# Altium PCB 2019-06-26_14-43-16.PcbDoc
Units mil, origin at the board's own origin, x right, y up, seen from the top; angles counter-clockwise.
Board outline 2600 x 1500 mil, 4 copper layers (Top Layer, MidLayer1, MidLayer2, Bottom Layer); 20 components, 9 nets, 52 pads, 82 vias.
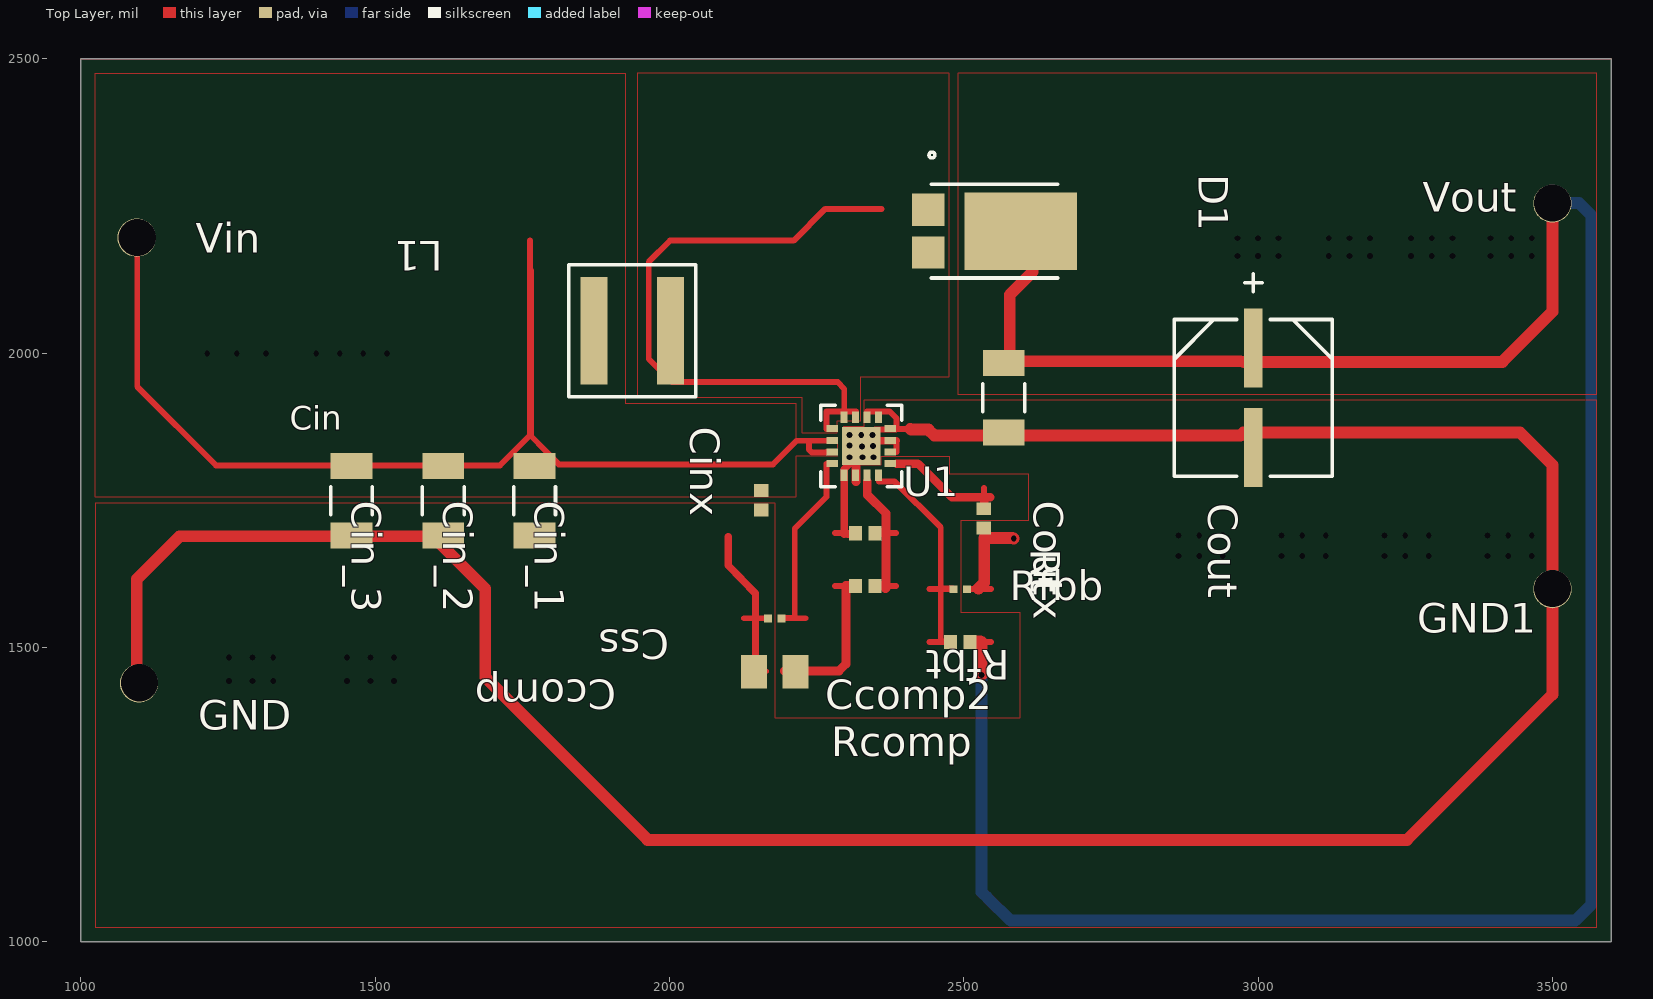
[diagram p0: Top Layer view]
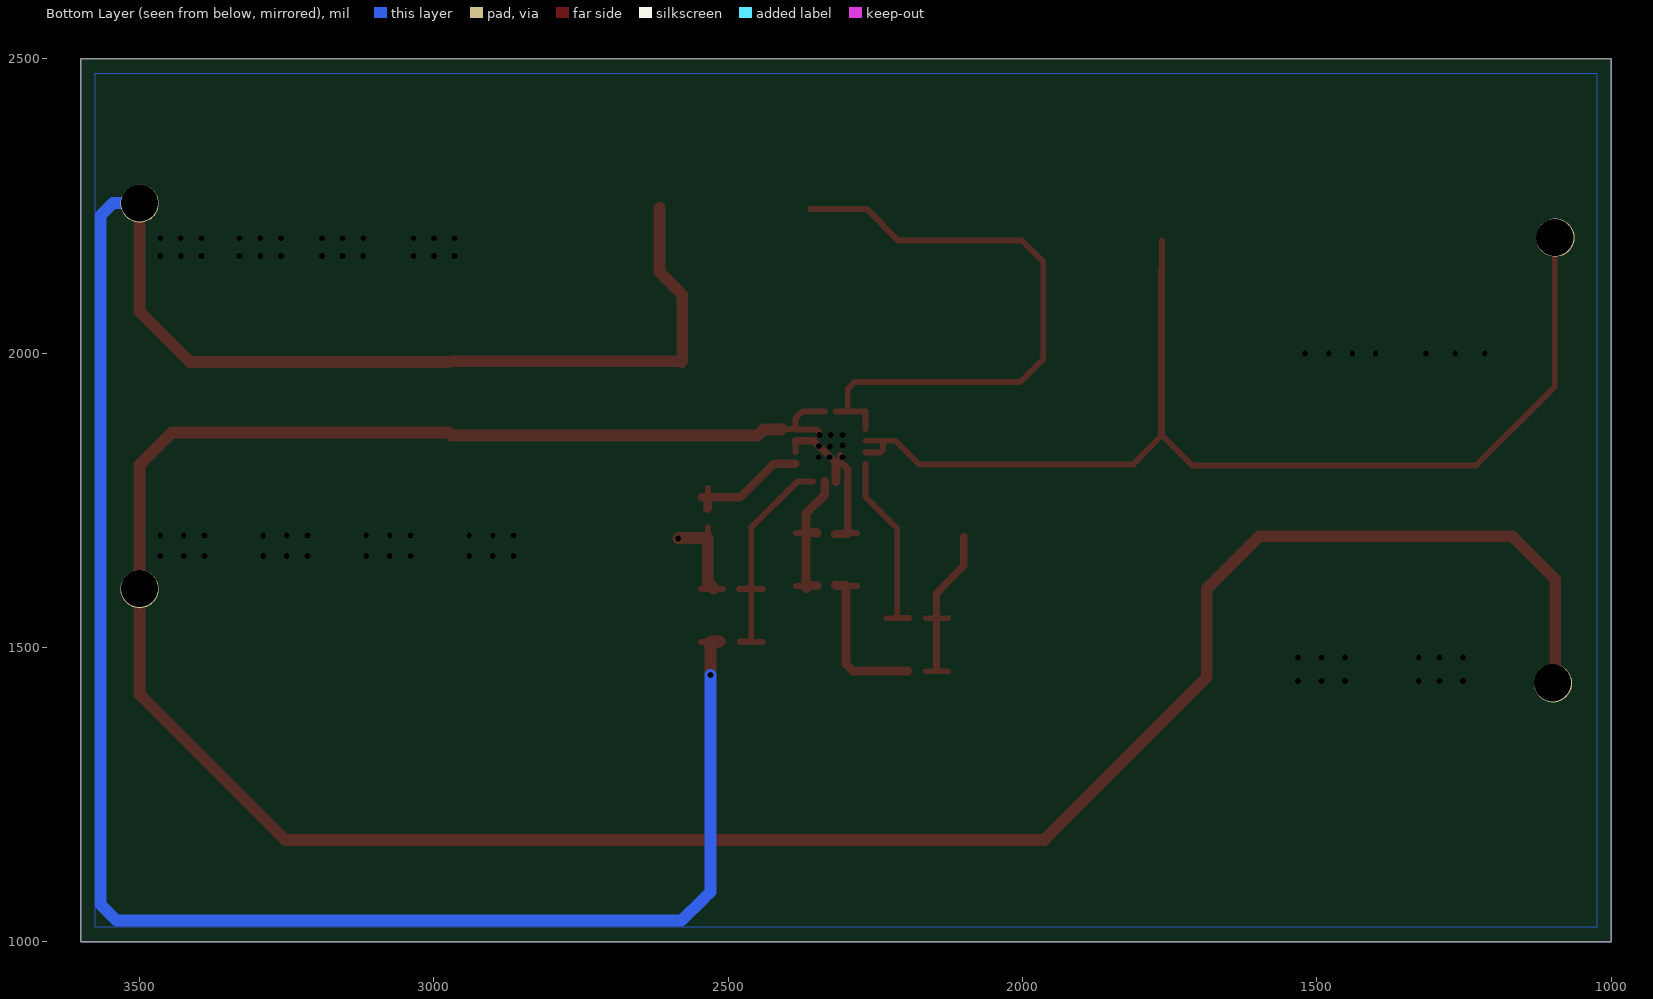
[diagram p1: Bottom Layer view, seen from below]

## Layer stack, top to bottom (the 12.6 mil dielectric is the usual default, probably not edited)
Top Layer: signal copper 1.4
Dielectric: core 12.6, FR-4, Dk 4.8
MidLayer1: signal copper 1.4
Dielectric: prepreg 12.6, FR-4, Dk 4.8
MidLayer2: signal copper 1.4
Dielectric: core 12.6, FR-4, Dk 4.8
Bottom Layer: signal copper 1.4

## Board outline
1000,1000 3600,1000 3600,2500 1000,2500

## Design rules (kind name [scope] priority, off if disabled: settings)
PlaneConnect [All] p0: scope1count=1 scope1_0_kind=Board scope1_0_value=Board scope2count=1 scope2_0_kind=Board scope2_0_value=Board commentlength=0 planeconnectstyle=Direct reliefexpansion=20 reliefentries=4 reliefconductorwidth=10 reliefairgap=10
PlaneConnect [All] p1: planeconnectstyle=Direct reliefexpansion=20 reliefentries=4 reliefconductorwidth=10 reliefairgap=10
PolygonConnect [All] p0: scope1count=1 scope1_0_kind=Board scope1_0_value=Board scope2count=1 scope2_0_kind=Board scope2_0_value=Board commentlength=0 connectstyle=Direct reliefconductorwidth=10 reliefentries=4 polygonreliefangle="90 Angle"
PolygonConnect [All] p1: connectstyle=Direct reliefconductorwidth=10 reliefentries=4 polygonreliefangle="90 Angle"

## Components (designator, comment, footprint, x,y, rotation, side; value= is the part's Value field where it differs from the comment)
Ccomp "" 0805 2179,1459 r180 top
Ccomp2 "" 0402 2333,1694 r0 top
Cin_1 "" 1206_190 1771,1749 r270 top
Cin_2 "" 1206_190 1616,1749 r270 top
Cin_3 "" 1206_190 1460,1749 r270 top
Cinx "" 0402 2156,1750 r270 top
Cout "" CAPSMT_62_F61 2992,1924 r270 top
Coutx "" 1206 2568,1924 r270 top
Css "" 0201 2179,1549 r180 top
D1 "" POWERDI5 2552,2207 r270 top
GND "" TP-5012 1099,1439 r0 top
GND1 "" TP-5012 3500,1599 r0 top
L1 "" XAL5030 1937,2038 r180 top
Rcomp "" 0402 2333,1604 r0 top
Rfbb "" 0201 2494,1599 r0 top
Rfbt "" 0402 2494,1509 r180 top
Rt "" 0402 2534,1719 r270 top
U1 "" S-PWQFN-N16 2326,1842 r0 top
Vin "" TP-5012 1095,2196 r0 top
Vout "" TP-5012 3500,2254 r0 top

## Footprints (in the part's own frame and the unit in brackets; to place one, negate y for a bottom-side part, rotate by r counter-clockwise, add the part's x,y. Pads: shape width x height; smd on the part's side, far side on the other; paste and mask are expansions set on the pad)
0201 [mil]
  rect 14x13 smd: 1(-11.5,0) 2(11.5,0)
0402 [mil]
  rect 22x24 smd: 1(-16.5,0) 2(16.5,0)
0805 [mil]
  rect 44x57 smd: 1(-35.5,0) 2(35.5,0)
1206 [mil]
  rect 44x71 smd: 1(-59,0) 2(59,0)
  silkscreen extent -24,-36 24,36
1206_190 [mil]
  rect 44x71 smd: 1(-59,0) 2(59,0)
  silkscreen extent -24,-36 24,36
CAPSMT_62_F61 [mil]
  rect 134x31 smd: 1(-84.5,0) 2(84.5,0)
  silkscreen extent -210,-134 133,134
POWERDI5 [mil]
  rect 55x55 smd: 1(-36.22,-112.5) 3(36.22,-112.5)
  rect 132x191 smd: 2(0,44.5)
  silkscreen extent -134,-111 80,108
S-PWQFN-N16 [mm]
  rect 0.5x0.3 smd: 1(-1.25,0.75) 2(-1.25,0.25) 3(-1.25,-0.25) 4(-1.25,-0.75) 9(1.25,-0.75) 10(1.25,-0.25) 11(1.25,0.25) 12(1.25,0.75)
  rect 0.3x0.5 smd: 5(-0.75,-1.25) 6(-0.25,-1.25) 7(0.25,-1.25) 8(0.75,-1.25) 13(0.75,1.25) 14(0.25,1.25) 15(-0.25,1.25) 16(-0.75,1.25)
  rect 1.65x1.65 smd: 17(0,0)
  silkscreen extent -1.75,-1.75 1.75,1.75
TP-5012 [mil]
  round 65 / inner round 0 / far side round 65 hole 32: 1(0,0)
XAL5030 [mil]
  rect 46x183 smd: 1(-65,0) 2(65,0)
  silkscreen extent -108,-112 108,112

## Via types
v1: diameter 0, hole 10, Top Layer to Bottom Layer, 78 vias
v2: diameter 0, hole 63, Top Layer to Bottom Layer, 4 vias

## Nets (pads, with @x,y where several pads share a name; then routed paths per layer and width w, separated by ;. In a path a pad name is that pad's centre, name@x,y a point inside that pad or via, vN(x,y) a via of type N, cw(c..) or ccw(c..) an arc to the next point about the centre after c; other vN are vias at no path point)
0: Ccomp2.1 Ccomp.2 Cin_1.2 Cin_2.2 Cin_3.2 Cinx.2 Cout.2 Coutx.2 Css.2 GND1.1 GND.1 Rfbb.2 Rt.2 U1.5 U1.6 U1.10 U1.11 U1.12 U1.13 U1.14 U1.17 | length 5539.2
  Top Layer w10: Ccomp.2@2127,1459.5 Ccomp.2@2164,1459.5 ; 2127,1549.5 Css.2@2164,1549.5 ; 2281,1694.5 Ccomp2.1@2318,1694.5 ; U1.14@2336,1901 2356,1901 2374,1901 2386,1889 2386,1871 ; U1.17@2346,1860 2346,1867 2349,1870 2385,1870 2386,1871 ; 2386,1832 2386,1851 ; 2409,1871 2386,1871 ; Rfbb.2@2509,1599.5 2546,1599.5 ; 2534.5,1667 Rt.2@2534.5,1704 ; 2975,1865 Cout.2@2980,1870
  Top Layer w12: 2100,1688 2100,1639 2146,1592 2146,1550 Ccomp.2@2146,1460 ; 2297,1692 2297,1695 ; 2297,1701 2297,1782 2297,1803 2310,1816 U1.17@2310,1826 ; 2300,1695 2303,1692 Ccomp2.1@2320,1692 ; U1.17@2317,1813 v1(2346,1842) 2355,1851 2386,1851
  Top Layer w15: 2317,1782 U1.17@2317,1813
  Top Layer w20: GND.1@1095,1440 1095,1616 1168,1689 1420,1689 1598,1689 1687,1600 1687,1449 1963,1173 3253,1173 3500,1420 v2(3500,1600) 3500,1810 3445,1865 2976,1865 2975,1865 2970,1860 2450,1860 2440,1870 2411,1870 2409,1871 ; 2525,1600 2535,1610 2535,1686 2583,1686 v1(2585,1685)
  other v1: 1252,1443 1292,1443 1327,1443 1452,1443 1492,1443 1532,1443 1252,1483 1292,1483 1327,1483 1452,1483 1492,1483 1532,1483 2865,1655 2900,1655 2940,1655 3040,1655 3075,1655 3115,1655 3215,1655 3250,1655 3290,1655 3390,1655 3425,1655 3465,1655 2865,1690 2900,1690 2940,1690 3040,1690 3075,1690 3115,1690 3215,1690 3250,1690 3290,1690 3390,1690 3425,1690 3465,1690 2306,1823 2328,1823 2347,1823 2327,1841 2306,1843 2306,1861 2326,1861 2345,1861
  other v2: 1100,1440
1: Css.1 U1.4 | length 341.4
  Top Layer w10: Css.1@2193,1550 2213,1550 2213,1702 2267,1756 U1.4@2267,1812 ; Css.1@2194,1549.5 2231,1549.5
2: Rfbb.1 Rfbt.2 U1.8 | length 448.4
  Top Layer w10: 2356,1782 2382,1782 2461,1704 2461,1597 ; 2442,1509.5 Rfbt.2@2479,1509.5 ; 2442,1599.5 Rfbb.1@2479,1599.5 ; Rfbt.2@2480,1510 2461,1510 2461,1600 2481,1600 Rfbb.1@2482,1599
3: Ccomp.1 Rcomp.1 | length 335.4
  Top Layer w10: Ccomp.1@2194,1459.5 Ccomp.1@2231,1459.5 ; 2281,1604.5 Rcomp.1@2318,1604.5
  Top Layer w15: Ccomp.1@2195,1460 2213,1460 2288,1460 2300,1472 2300,1605 2317,1605 Rcomp.1@2318,1606
4: Cin_1.1 Cin_2.1 Cin_3.1 Cinx.1 L1.2 U1.2 U1.3 Vin.1 | length 2190.9
  Top Layer w10: v2(1096,2196) 1096,1943 1230,1809 1420,1809 1712,1809 1763,1860 1763,2191 ; 1765,2140 1765,1859 1812,1811 2100,1811 2176,1811 2216,1851 U1.2@2267,1851 ; 2237,1847 2237,1836 2242,1831 2266,1831 U1.3@2267,1832
  other v1: 1215,1999 1265,1999 1315,1999 1400,1999 1440,1999 1480,1999 1520,1999
5: Rt.1 U1.9 | length 237.7
  Top Layer w10: Rt.1@2534.5,1734 2534.5,1771
  Top Layer w14: 2386,1812 2422,1812 2480,1755 2545,1755 ; 2535,1753 2535,1736 Rt.1@2536,1735
6: Cout.1 Coutx.1 D1.2 Rfbt.1 Vout.1 | length 4195
  Top Layer w10: Rfbt.1@2509,1509.5 2546,1509.5
  Top Layer w20: Rfbt.1@2515,1510 2528,1510 ; v1(2530,1453) 2530,1509 ; Coutx.1@2578,1986 2578,2099 2617,2138 D1.2@2617,2247 ; Coutx.1@2579,1985 2580,1986 2970,1986 ; 2976,1985 3415,1985 3500,2070 Vout.1@3500,2250
  Bottom Layer w20: v1(2530,1453) 2530,1084 2540,1075 2580,1036 3539,1036 3566,1063 3566,2234 3545,2255 v2(3500,2255)
  other v1: 2965,2165 3000,2165 3035,2165 3120,2165 3155,2165 3190,2165 3260,2165 3295,2165 3330,2165 3395,2165 3430,2165 3465,2165 2965,2195 3000,2195 3035,2195 3120,2195 3155,2195 3190,2195 3260,2195 3295,2195 3330,2195 3395,2195 3430,2195 3465,2195
8: D1.1 D1.3 L1.1 U1.1 U1.15 U1.16 | length 1068.7
  Top Layer w10: U1.1@2267,1871 2267,1901 U1.16@2297,1901 ; U1.15@2317,1901 U1.16@2297,1901 ; 2360,2245 2265,2245 2211,2191 2106,2191 2001,2191 1965,2155 1965,1990 2004,1951 2286,1951 2297,1939 U1.16@2297,1901
9: Ccomp2.2 Rcomp.2 U1.7 | length 306.4
  Top Layer w10: Rcomp.2@2348,1604.5 2385,1604.5 ; Ccomp2.2@2348,1694.5 2385,1694.5
  Top Layer w15: 2336,1782 2336,1759 2368,1728 2368,1695 2368,1601 2367,1600 ; Rcomp.2@2349,1605 2367,1605 ; Ccomp2.2@2349,1694 2350,1695 2367,1695

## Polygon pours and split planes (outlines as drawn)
8 on Top Layer " " (solid, pour order 4): 1945,1925 2225,1925 2225,1865 2285,1865 2285,1885 2325,1885 2325,1960 2475,1960 2475,2475 1945,2475
6 on Top Layer " " (solid, pour order 5): 2490,2475 2490,1930 3575,1930 3575,2475
4 on Top Layer " " (solid, pour order 6): 2285,1825 2215,1825 2215,1755 1025,1755 1025,2475 1925,2475 1925,1915 2215,1915 2215,1855 2285,1855
0 on Top Layer " " (solid, pour order 9): 1025,1745 1025,1025 3575,1025 3575,1920 2330,1920 2330,1875 2295,1875 2295,1810 2360,1810 2360,1825 2475,1825 2475,1795 2610,1795 2610,1715 2495,1715 2495,1560 2595,1560 2595,1380 2180,1380 2180,1745
0 on Bottom Layer " " (solid, pour order 10): 1025,1025 3575,1025 3575,2475 1025,2475
6 on MidLayer2 " " (solid, pour order 0): 2490,2475 2490,1930 3575,1930 3575,2475
4 on MidLayer2 " " (solid, pour order 1): 1025,2475 1560,2475 1560,1755 1025,1755
6 on MidLayer1 " " (solid, pour order 2): 2490,2475 2490,1930 3575,1930 3575,2475
4 on MidLayer1 " " (solid, pour order 3): 1025,2475 1560,2475 1560,1755 1025,1755
0 on MidLayer2 " " (solid, pour order 7): 1570,2475 1570,1745 1025,1745 1025,1025 3575,1025 3575,1920 2475,1920 2475,2475
0 on MidLayer1 " " (solid, pour order 8): 1570,2475 1570,1745 1025,1745 1025,1025 3575,1025 3575,1920 2475,1920 2475,2475
no net on Top Paste "Top Layer-No Net" (solid, remove dead copper): 2365.37,1857.75 2365.37,1845.94 2385.06,1845.94 2385.06,1857.75
no net on Top Paste "Top Layer-No Net" (solid, remove dead copper): 2365.37,1877.43 2365.37,1865.62 2385.06,1865.62 2385.06,1877.43
no net on Top Paste "Top Layer-No Net" (solid, remove dead copper): 2349.62,1901.06 2349.62,1881.37 2361.43,1881.37 2361.43,1901.06
no net on Top Paste "Top Layer-No Net" (solid, remove dead copper): 2329.94,1901.06 2329.94,1881.37 2341.75,1881.37 2341.75,1901.06
no net on Top Paste "Top Layer-No Net" (solid, remove dead copper): 2310.25,1901.06 2310.25,1881.37 2322.06,1881.37 2322.06,1901.06
no net on Top Paste "Top Layer-No Net" (solid, remove dead copper): 2290.57,1901.06 2290.57,1881.37 2302.38,1881.37 2302.38,1901.06
no net on Top Paste "Top Layer-No Net" (solid, remove dead copper): 2306.32,1861.68 2306.32,1822.32 2345.68,1822.32 2345.68,1861.68

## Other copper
Multi-Layer:
  the board outline again, w1

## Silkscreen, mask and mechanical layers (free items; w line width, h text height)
Top Overlay:
  text "Cin" at 1355,1870 h40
